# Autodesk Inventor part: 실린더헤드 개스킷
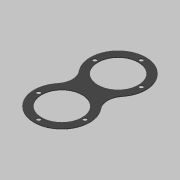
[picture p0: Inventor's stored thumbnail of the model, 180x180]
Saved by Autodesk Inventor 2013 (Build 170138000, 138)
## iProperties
Created: 2019-08
Part Number: 실린더헤드 개스킷
Material: 고무
Document SubType Name: Modeling
Designer: mduedu
Density: 1 g/cm^3
Author: mduedu
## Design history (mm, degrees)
sketch "스케치1"
  geometry: L1 (0, 0)-(0, 85); C1 r 30.5 at (0, 85); C2 r 30.5 at (0, 0); A1 r 42 centre (0, 0) between (0, 42) and (-32.469, 26.642); A2 r 42 centre (0, 85) between (0, 43) and (32.469, 58.358); A3 r 25 centre (51.795, 42.5) between (32.469, 58.358) and (32.469, 26.642); A4 r 25 centre (-51.795, 42.5) between (-32.469, 26.642) and (-32.469, 58.358); A5 r 42 centre (0, 0) between (32.469, 26.642) and (0, 42); A6 r 42 centre (0, 0) between (-32.469, 26.642) and (32.469, 26.642); A7 r 42 centre (0, 85) between (-32.469, 58.358) and (0, 43); A8 r 42 centre (0, 85) between (32.469, 58.358) and (-32.469, 58.358); A9 r 25 centre (51.795, 42.5) between (32.469, 26.642) and (32.469, 58.358); A10 r 25 centre (-51.795, 42.5) between (-32.469, 58.358) and (-32.469, 26.642); 1 further point
  constraints: 20 point on circle, 12 centre point, 4 coincident, 4 tangent, 2 end point, 2 point on line, 1 vertical
  dimensions: "d1" = 84 diameter of A1; "d3" = 85 distance of L1.start L1.end; "d4" = 84 diameter of A2; "d5" = 50 diameter of A3; "d6" = 50 diameter of A4 (= d5); "d11" = 61 diameter of C1; "d12" = 61 diameter of C2
extrude "돌출2" new body sketch "스케치1" distance "d13" = 1; taper "d14" = 0 deg
sketch "스케치2"
  geometry: A1 r 35 centre (0, 0) between (-35, 0) and (0, 35); 2 further points
  constraints: 3 point on circle, 2 horizontal alignment, 1 centre point, 1 coincident, 1 vertical alignment
  dimensions: "d15" = 70 diameter of A1
hole "구멍1" sketch "스케치2" at (-35, 0), (0, 35), (35, 0) diameter "d16" = 6; stored, may be unused: countersink angle "d20" = 90 deg, drill point angle "d22" = 118 deg; dims "d17" = 6, "d18" = 4, "d19" = 2, "d21" = 8
node "작업 평면1"
mirror "대칭1"
node "솔리드2"
other parameters: "d23" = 42.5
